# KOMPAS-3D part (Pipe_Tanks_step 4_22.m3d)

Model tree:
1. X Axis
2. Y Axis
3. Z Axis  (labels: Pipe Dn 20; Valve Dy 50)
     Òîëùèíà ñòåíêè 1 = 1

Referenced files in C:\Documents and Settings\kashirsky\Мои документы\Camtasia Studio\Pipelines3D\Tanks\: Tanks_step 4.a3d
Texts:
  Pipe Dn 20
  Steel ASTM A295
  Three Point Plane
  Plane at Angle
  Line and Point Plane
  Axis through Two Vertices
  Axis of Feature
  Axis of Conical Surface
  Axis through Edge
  Trim by Surface
  Trim by Sketch
  Feature with No History
  Intersection Axis of Two Planes
  Two Line Plane
  Line and Face Plane
  Bend by line
  Hole in sheet body
  Cut in sheet body
  Point in CM
  Linear Dimension from Line to Point
  Surface Finish Symbol
  Geometric Tolerance Symbol
  Leader #1
  Leader #2
  Leader #3
  Shape Deviations and Datum
  Node point number
  Mark of coordination axis
  Node point designation
  Mark/Reference designation with leader
  Mark/reference designation on line
  Mark/Reference designation without leader
  Valve Dy 50
  Plane of section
